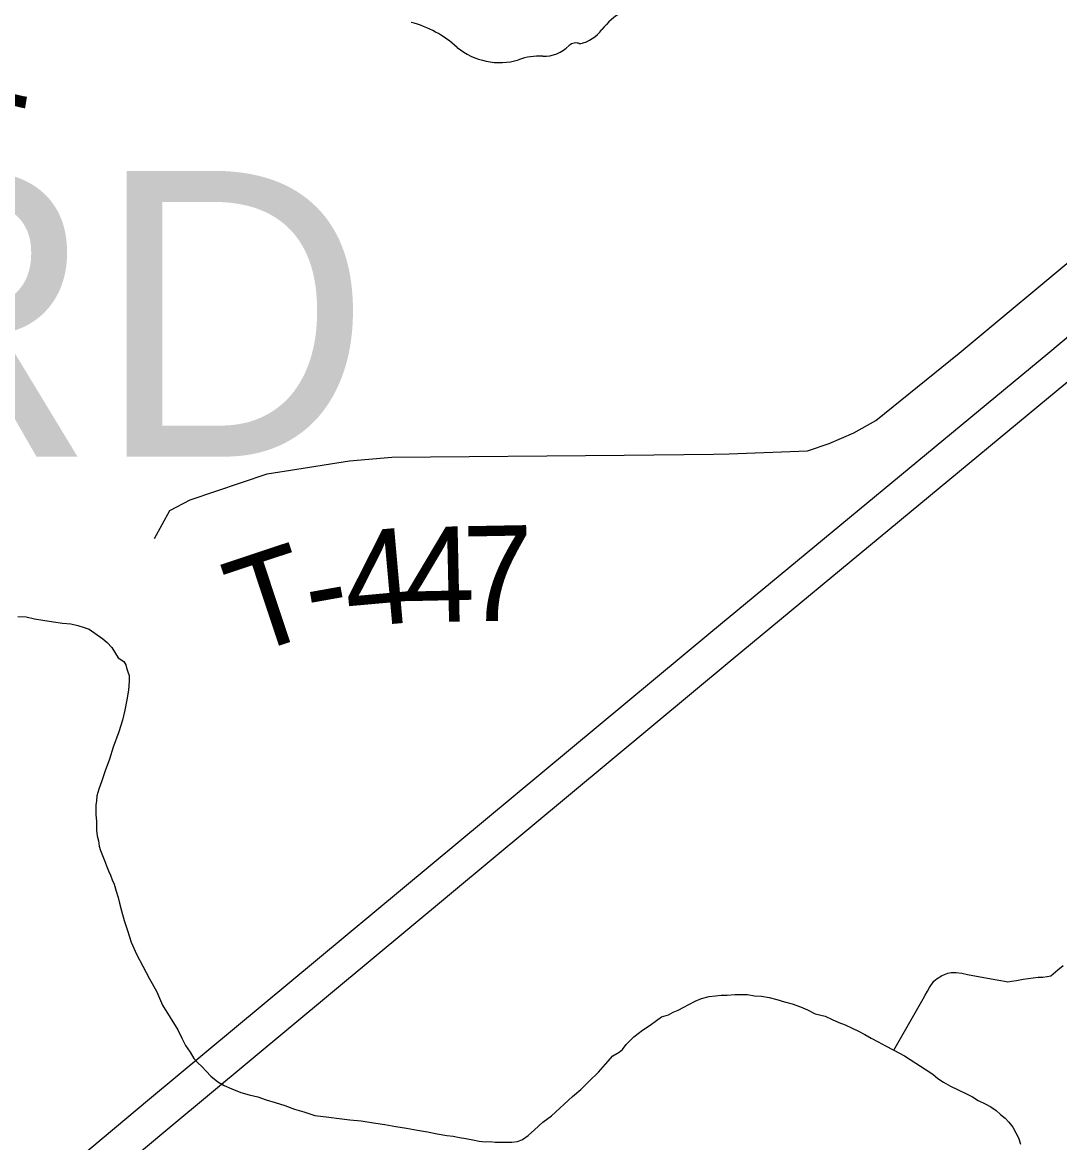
# Model space of a CAD drawing. Extents: x -59 to 82, y -3 to 49.
# Drawn here: x -52.032 to -51.414, y 43.271 to 43.939 of the extents above; entities that cross this region are included whole.
import ezdxf

# ---------------------------------------------------------------- set-up
doc = ezdxf.new("R2010")
doc.units = 0
for name, color, linetype in [('GM_X_Interstate_Route', 7, 'Continuous'), ('GM_X_Minor_River', 7, 'Continuous'), ('GM_X_State_Shield', 7, 'Continuous'), ('GM_X_Township_Road', 7, 'Continuous'), ('GM_X_Township_Road_Text', 7, 'Continuous'), ('SH_Data', 7, 'Continuous')]:
    doc.layers.add(name, color=color, linetype=linetype)

msp = doc.modelspace()

# ---------------------------------------------------------------- linework, layer by layer
at = {"layer": 'GM_X_Interstate_Route'}
for p, q in [((-51.42069, 43.74167), (-51.19391, 43.93124)), ((-51.62148, 43.57535), (-51.42069, 43.74167)), ((-51.60938, 43.55863), (-51.40859, 43.72495)), ((-51.95636, 43.29691), (-51.62148, 43.57535)), ((-51.94425, 43.28019), (-51.60938, 43.55863)), ((-52.02981, 43.23551), (-51.95636, 43.29691)), ((-52.0177, 43.21879), (-51.94425, 43.28019))]:
    msp.add_line(p, q, dxfattribs=at)
at = {"layer": 'GM_X_Minor_River'}
for p, q in [((-52.03484, 43.58475), (-52.0299, 43.58441)), ((-52.0299, 43.58441), (-52.02495, 43.5833)), ((-52.02495, 43.5833), (-52.02001, 43.58258)), ((-52.02001, 43.58258), (-52.01355, 43.58148)), ((-52.01355, 43.58148), (-52.00823, 43.58076)), ((-52.00823, 43.58076), (-52.00329, 43.58041)), ((-52.00329, 43.58041), (-51.9991, 43.5793)), ((-51.9991, 43.5793), (-51.99529, 43.57819)), ((-51.99529, 43.57819), (-51.99225, 43.57707)), ((-51.99225, 43.57707), (-51.98423, 43.57142)), ((-51.98423, 43.57142), (-51.98155, 43.56916)), ((-51.98155, 43.56916), (-51.97887, 43.56613)), ((-51.97887, 43.56613), (-51.97502, 43.56007)), ((-51.97502, 43.56007), (-51.97159, 43.55782)), ((-51.97159, 43.55782), (-51.97043, 43.55592)), ((-51.97043, 43.55592), (-51.97004, 43.55402)), ((-51.97004, 43.55402), (-51.96926, 43.55175)), ((-51.96926, 43.55175), (-51.96848, 43.54947)), ((-51.96845, 43.54605), (-51.96879, 43.54072)), ((-51.96848, 43.54947), (-51.96845, 43.54605)), ((-51.96879, 43.54072), (-51.96988, 43.53501)), ((-51.96988, 43.53501), (-51.97097, 43.52891)), ((-51.97097, 43.52891), (-51.97244, 43.52282)), ((-51.97244, 43.52282), (-51.97467, 43.51595)), ((-51.97467, 43.51595), (-51.97801, 43.5068)), ((-51.97801, 43.5068), (-51.98023, 43.49956)), ((-51.98023, 43.49956), (-51.98283, 43.49269)), ((-51.98283, 43.49269), (-51.98468, 43.48659)), ((-51.98468, 43.48659), (-51.98654, 43.48163)), ((-51.98654, 43.48163), (-51.98765, 43.47782)), ((-51.988, 43.47478), (-51.98836, 43.47211)), ((-51.98836, 43.47211), (-51.98834, 43.46945)), ((-51.98765, 43.47782), (-51.988, 43.47478)), ((-51.98834, 43.46945), (-51.98831, 43.46641)), ((-51.98831, 43.46641), (-51.9879, 43.46261)), ((-51.9879, 43.46261), (-51.98786, 43.45728)), ((-51.98786, 43.45728), (-51.98745, 43.45386)), ((-51.98745, 43.45386), (-51.98667, 43.45082)), ((-51.98667, 43.45082), (-51.98626, 43.44778)), ((-51.98626, 43.44778), (-51.98548, 43.44513)), ((-51.98548, 43.44513), (-51.98432, 43.44209)), ((-51.98432, 43.44209), (-51.98316, 43.43906)), ((-51.98316, 43.43906), (-51.98199, 43.43602)), ((-51.98199, 43.43602), (-51.98083, 43.43299)), ((-51.98083, 43.43299), (-51.97967, 43.43033)), ((-51.97967, 43.43033), (-51.97851, 43.42768)), ((-51.97851, 43.42768), (-51.97735, 43.42502)), ((-51.97735, 43.42502), (-51.97617, 43.42085)), ((-51.97617, 43.42085), (-51.97501, 43.41706)), ((-51.97501, 43.41706), (-51.97422, 43.41364)), ((-51.97422, 43.41364), (-51.97304, 43.40908)), ((-51.97304, 43.40908), (-51.97147, 43.40339)), ((-51.97147, 43.40339), (-51.96953, 43.39731)), ((-51.96953, 43.39731), (-51.96719, 43.39049)), ((-51.96719, 43.39049), (-51.9641, 43.38328)), ((-51.9641, 43.38328), (-51.96024, 43.37608)), ((-51.96024, 43.37608), (-51.95639, 43.3685)), ((-51.48402, 43.37035), (-51.48213, 43.37112)), ((-51.48213, 43.37112), (-51.48024, 43.3719)), ((-51.48024, 43.3719), (-51.47834, 43.37229)), ((-51.47834, 43.37229), (-51.4753, 43.37231)), ((-51.4753, 43.37231), (-51.47189, 43.37196)), ((-51.47189, 43.37196), (-51.46846, 43.37122)), ((-51.46846, 43.37122), (-51.45439, 43.36866)), ((-51.41871, 43.37043), (-51.41456, 43.37388)), ((-51.41456, 43.37388), (-51.41155, 43.37657)), ((-51.95639, 43.3685), (-51.95215, 43.36131)), ((-51.49118, 43.36345), (-51.48856, 43.36727)), ((-51.48856, 43.36727), (-51.48667, 43.36881)), ((-51.48667, 43.36881), (-51.48402, 43.37035)), ((-51.45439, 43.36866), (-51.45097, 43.36792)), ((-51.45097, 43.36792), (-51.44868, 43.36756)), ((-51.44868, 43.36756), (-51.44641, 43.36719)), ((-51.44641, 43.36719), (-51.4445, 43.36683)), ((-51.4445, 43.36683), (-51.44223, 43.36722)), ((-51.44223, 43.36722), (-51.43919, 43.36763)), ((-51.43919, 43.36763), (-51.4354, 43.36841)), ((-51.4354, 43.36841), (-51.43237, 43.36881)), ((-51.43237, 43.36881), (-51.42933, 43.36922)), ((-51.42933, 43.36922), (-51.4263, 43.36962)), ((-51.4263, 43.36962), (-51.42364, 43.36964)), ((-51.42364, 43.36964), (-51.42099, 43.37004)), ((-51.42099, 43.37004), (-51.41871, 43.37043)), ((-51.95215, 43.36131), (-51.94866, 43.35296)), ((-51.62707, 43.35678), (-51.62252, 43.35795)), ((-51.62252, 43.35795), (-51.61873, 43.35836)), ((-51.61873, 43.35836), (-51.61531, 43.35877)), ((-51.61531, 43.35877), (-51.6119, 43.35879)), ((-51.6119, 43.35879), (-51.60734, 43.3592)), ((-51.60734, 43.3592), (-51.60355, 43.35923)), ((-51.60355, 43.35923), (-51.59975, 43.35926)), ((-51.59975, 43.35926), (-51.59557, 43.35852)), ((-51.59557, 43.35852), (-51.59139, 43.35817)), ((-51.59139, 43.35817), (-51.58682, 43.35745)), ((-51.49492, 43.35658), (-51.4938, 43.35887)), ((-51.4938, 43.35887), (-51.4923, 43.36116)), ((-51.4923, 43.36116), (-51.49118, 43.36345)), ((-51.94866, 43.35296), (-51.93943, 43.3382)), ((-51.64106, 43.34983), (-51.63766, 43.35176)), ((-51.63766, 43.35176), (-51.63464, 43.3533)), ((-51.63464, 43.3533), (-51.63085, 43.35523)), ((-51.63085, 43.35523), (-51.62707, 43.35678)), ((-51.58682, 43.35745), (-51.58226, 43.35634)), ((-51.58226, 43.35634), (-51.57769, 43.35485)), ((-51.57769, 43.35485), (-51.57312, 43.35374)), ((-51.57312, 43.35374), (-51.56817, 43.35187)), ((-51.56817, 43.35187), (-51.56398, 43.35)), ((-51.51252, 43.32603), (-51.49492, 43.35658)), ((-51.65392, 43.34366), (-51.6509, 43.34596)), ((-51.6509, 43.34596), (-51.64674, 43.34713)), ((-51.64674, 43.34713), (-51.64409, 43.34867)), ((-51.64409, 43.34867), (-51.64106, 43.34983)), ((-51.56398, 43.35), (-51.5594, 43.34775)), ((-51.5594, 43.34775), (-51.55332, 43.34628)), ((-51.55332, 43.34628), (-51.54913, 43.3444)), ((-51.54913, 43.3444), (-51.54531, 43.34253)), ((-51.93943, 43.3382), (-51.93711, 43.33327)), ((-51.66751, 43.33405), (-51.66223, 43.33789)), ((-51.66223, 43.33789), (-51.6577, 43.34097)), ((-51.6577, 43.34097), (-51.65392, 43.34366)), ((-51.54531, 43.34253), (-51.5415, 43.34104)), ((-51.5415, 43.34104), (-51.53731, 43.33916)), ((-51.53731, 43.33916), (-51.5335, 43.33729)), ((-51.93711, 43.33327), (-51.9348, 43.32872)), ((-51.67204, 43.32945), (-51.66751, 43.33405)), ((-51.5335, 43.33729), (-51.52969, 43.33542)), ((-51.52969, 43.33542), (-51.52587, 43.33316)), ((-51.52587, 43.33316), (-51.52168, 43.33091)), ((-51.9348, 43.32872), (-51.93211, 43.32493)), ((-51.93211, 43.32493), (-51.9298, 43.32115)), ((-51.67995, 43.32255), (-51.67618, 43.32486)), ((-51.67618, 43.32486), (-51.67429, 43.3264)), ((-51.67429, 43.3264), (-51.67204, 43.32945)), ((-51.52168, 43.33091), (-51.51748, 43.32866)), ((-51.51748, 43.32866), (-51.51252, 43.32603)), ((-51.51252, 43.32603), (-51.50604, 43.32265)), ((-51.9298, 43.32115), (-51.9275, 43.3185)), ((-51.9275, 43.3185), (-51.9252, 43.31624)), ((-51.68447, 43.31758), (-51.67995, 43.32255)), ((-51.50604, 43.32265), (-51.49306, 43.31438)), ((-51.9252, 43.31624), (-51.92252, 43.31359)), ((-51.92252, 43.31359), (-51.91984, 43.31057)), ((-51.69426, 43.30724), (-51.68861, 43.31298)), ((-51.68861, 43.31298), (-51.68447, 43.31758)), ((-51.49306, 43.31438), (-51.48925, 43.31174)), ((-51.48925, 43.31174), (-51.48618, 43.3091)), ((-51.91984, 43.31057), (-51.91564, 43.30718)), ((-51.91564, 43.30718), (-51.91182, 43.30492)), ((-51.91182, 43.30492), (-51.90725, 43.30305)), ((-51.69916, 43.30264), (-51.69426, 43.30724)), ((-51.48618, 43.3091), (-51.48275, 43.30684)), ((-51.48275, 43.30684), (-51.47856, 43.30459)), ((-51.47856, 43.30459), (-51.47398, 43.30234)), ((-51.90725, 43.30305), (-51.90192, 43.30081)), ((-51.90192, 43.30081), (-51.89697, 43.29932)), ((-51.89697, 43.29932), (-51.89164, 43.29822)), ((-51.89164, 43.29822), (-51.88669, 43.29635)), ((-51.7165, 43.28692), (-51.70406, 43.29842)), ((-51.70406, 43.29842), (-51.69916, 43.30264)), ((-51.47398, 43.30234), (-51.4694, 43.30009)), ((-51.4694, 43.30009), (-51.46559, 43.29822)), ((-51.46559, 43.29822), (-51.46216, 43.29596)), ((-51.88669, 43.29635), (-51.88136, 43.29487)), ((-51.88136, 43.29487), (-51.87565, 43.29301)), ((-51.87565, 43.29301), (-51.86994, 43.29077)), ((-51.46216, 43.29596), (-51.45796, 43.29409)), ((-51.45796, 43.29409), (-51.45453, 43.29221)), ((-51.45453, 43.29221), (-51.45148, 43.28995)), ((-51.86994, 43.29077), (-51.86423, 43.28929)), ((-51.86423, 43.28929), (-51.85776, 43.28705)), ((-51.85776, 43.28705), (-51.84939, 43.28597)), ((-51.84939, 43.28597), (-51.84331, 43.28525)), ((-51.84331, 43.28525), (-51.83685, 43.28454)), ((-51.83685, 43.28454), (-51.83001, 43.28383)), ((-51.72178, 43.28308), (-51.7165, 43.28692)), ((-51.45148, 43.28995), (-51.4488, 43.28769)), ((-51.4488, 43.28769), (-51.44612, 43.28543)), ((-51.44612, 43.28543), (-51.44383, 43.28316)), ((-51.83001, 43.28383), (-51.82279, 43.28274)), ((-51.82279, 43.28274), (-51.81594, 43.28165)), ((-51.81594, 43.28165), (-51.80948, 43.28055)), ((-51.80948, 43.28055), (-51.80301, 43.27946)), ((-51.80301, 43.27946), (-51.79655, 43.27836)), ((-51.79655, 43.27836), (-51.79047, 43.27726)), ((-51.73045, 43.27503), (-51.72668, 43.27848)), ((-51.72668, 43.27848), (-51.72178, 43.28308)), ((-51.44383, 43.28316), (-51.44152, 43.28014)), ((-51.44152, 43.28014), (-51.4396, 43.27673)), ((-51.79047, 43.27726), (-51.78476, 43.27617)), ((-51.78476, 43.27617), (-51.77906, 43.27506)), ((-51.77906, 43.27506), (-51.77526, 43.27471)), ((-51.77526, 43.27471), (-51.77145, 43.27398)), ((-51.77145, 43.27398), (-51.76765, 43.27324)), ((-51.76765, 43.27324), (-51.76347, 43.27251)), ((-51.76347, 43.27251), (-51.75966, 43.27178)), ((-51.75966, 43.27178), (-51.75624, 43.27142)), ((-51.75624, 43.27142), (-51.75321, 43.27145)), ((-51.75321, 43.27145), (-51.75017, 43.27109)), ((-51.75017, 43.27109), (-51.74675, 43.27111)), ((-51.74675, 43.27111), (-51.74333, 43.27113)), ((-51.74333, 43.27113), (-51.74029, 43.27116)), ((-51.74029, 43.27116), (-51.73688, 43.27156)), ((-51.73688, 43.27156), (-51.73385, 43.27272)), ((-51.73385, 43.27272), (-51.73045, 43.27503)), ((-51.4396, 43.27673), (-51.43805, 43.2737)), ((-51.43805, 43.2737), (-51.43689, 43.2699))]:
    msp.add_line(p, q, dxfattribs=at)
at = {"layer": 'GM_X_State_Shield'}
for centre, radius, start, end in [((-51.65611, 43.91153), 0.0383, 94.40312, 142.57675), ((-51.81582, 43.87781), 0.06318, 47.18416, 75.83597), ((-51.70464, 43.94832), 0.0226, 282.87319, 323.27711), ((-51.70208, 43.92081), 0.00601, 65.75173, 132.64842), ((-51.74749, 43.95518), 0.04009, 230.70037, 286.29184), ((-51.7214, 43.94019), 0.02136, 268.77702, 315.54927), ((-51.72433, 43.88599), 0.03294, 85.69512, 111.20995)]:
    msp.add_arc(centre, radius, start, end, dxfattribs=at)
at = {"layer": 'GM_X_Township_Road'}
for p, q in [((-51.47355, 43.7418), (-51.37708, 43.82228)), ((-51.52308, 43.70166), (-51.47355, 43.7418)), ((-51.5362, 43.69422), (-51.52308, 43.70166)), ((-51.55099, 43.68791), (-51.5362, 43.69422)), ((-51.56399, 43.68345), (-51.55099, 43.68791)), ((-51.83702, 43.67761), (-51.81191, 43.67967)), ((-51.81191, 43.67967), (-51.67322, 43.68091)), ((-51.67322, 43.68091), (-51.61989, 43.68161)), ((-51.61989, 43.68161), (-51.61066, 43.68173)), ((-51.61066, 43.68173), (-51.56399, 43.68345)), ((-51.88619, 43.66974), (-51.86838, 43.67261)), ((-51.86838, 43.67261), (-51.83702, 43.67761)), ((-51.93212, 43.65424), (-51.88619, 43.66974)), ((-51.94418, 43.64792), (-51.93212, 43.65424)), ((-51.95337, 43.63126), (-51.94418, 43.64792))]:
    msp.add_line(p, q, dxfattribs=at)

# ---------------------------------------------------------------- texts
at = {"layer": 'GM_X_Township_Road_Text'}
for s, rotation, p in [('7', 80.40591, (-52.03281, 43.87445)), ('4', 1.23338, (-51.80405, 43.58095)), ('7', 1.05648, (-51.7691, 43.5817)), ('4', 5.12753, (-51.83789, 43.57788)), ('T', 18.37261, (-51.8978, 43.56107)), ('-', 10.16172, (-51.85955, 43.57393))]:
    msp.add_text(s, height=0.05682, rotation=rotation, dxfattribs=at).set_placement(p)
at = {"layer": 'SH_Data'}
msp.add_text('CONCORD', height=0.170455, dxfattribs=at).set_placement((-53.00172, 43.68007))

doc.saveas('drawing.dxf')
